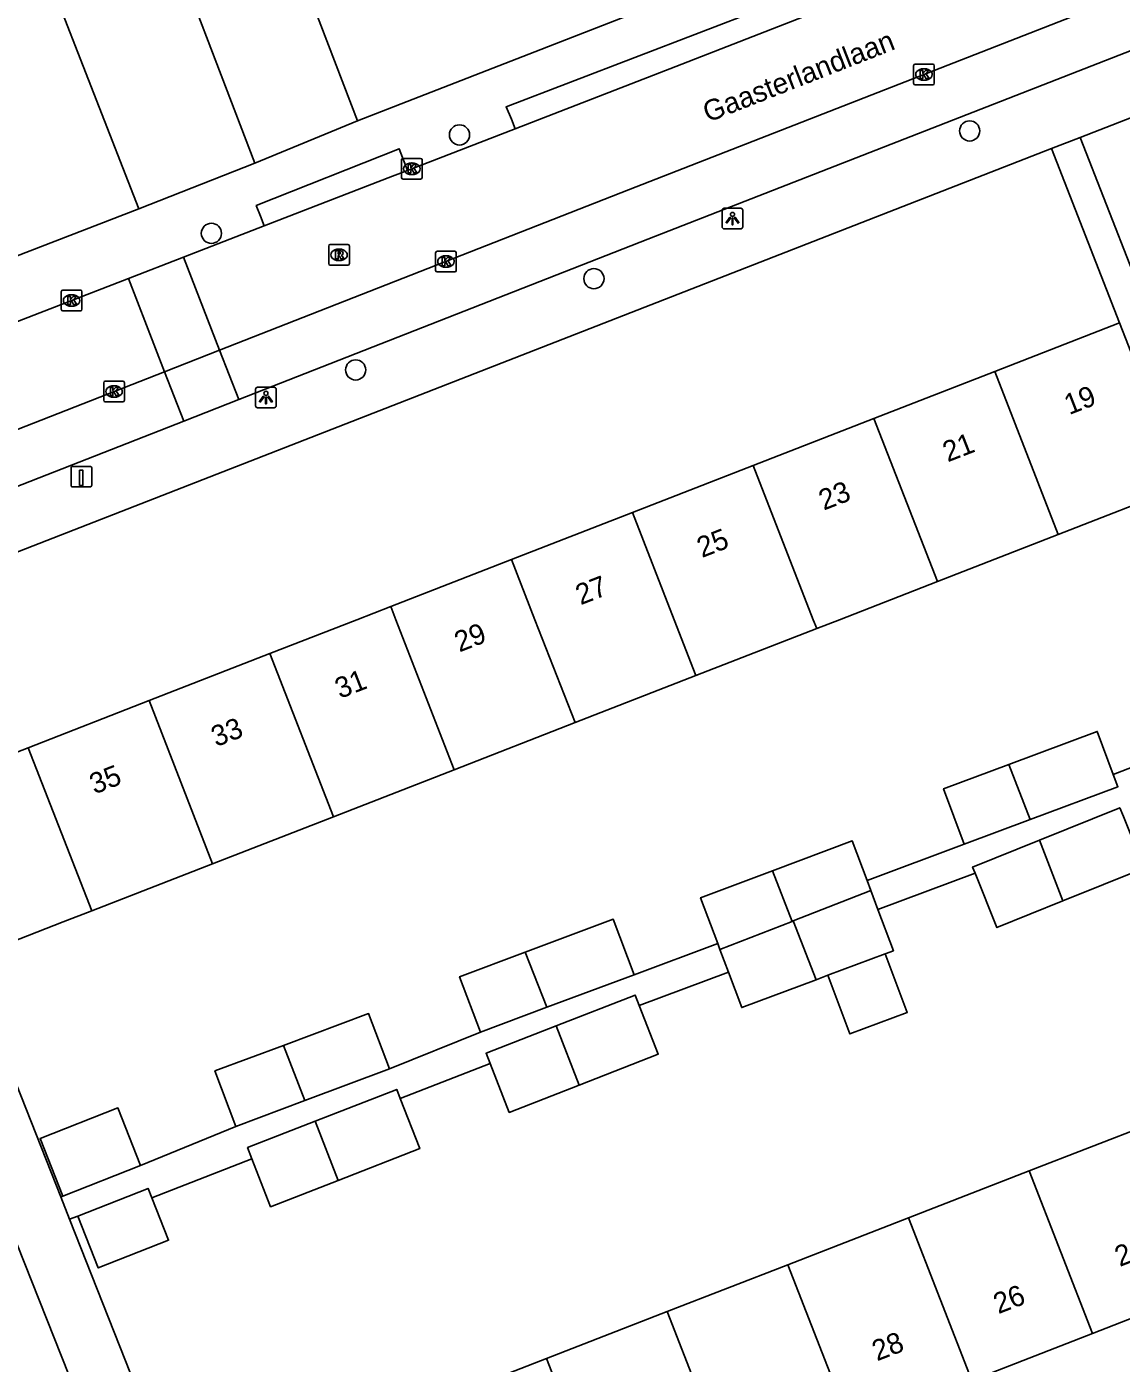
# Model space of a CAD drawing. Extents: x 159689 to 160786, y 387323 to 388339.
# Drawn here: x 160154.9 to 160207.9, y 387464 to 387528.7 of the extents above; entities that cross this region are included whole.
import ezdxf

# ---------------------------------------------------------------- set-up
doc = ezdxf.new("R2010")
doc.units = 0
for name, color, linetype in [('IMGEO_Boom', 7, 'Continuous'), ('IMGEO_Kolk', 7, 'Continuous'), ('IMGEO_Laadpaal', 7, 'Continuous'), ('IMGEO_Lichtpunt', 7, 'Continuous'), ('IMGEO_Openbare_ruimte_label', 7, 'Continuous'), ('IMGEO_Pand', 7, 'Continuous'), ('IMGEO_Pand_nummerreeks', 7, 'Continuous'), ('IMGEO_Parkeervlak_open', 7, 'Continuous'), ('IMGEO_Rijbaan_lokaal_open', 7, 'Continuous'), ('IMGEO_Rioolput', 7, 'Continuous'), ('IMGEO_Voetpad_open', 7, 'Continuous')]:
    doc.layers.add(name, color=color, linetype=linetype)

msp = doc.modelspace()

# ---------------------------------------------------------------- linework, layer by layer
at = {"layer": 'IMGEO_Boom'}
for centre in [(160175.85, 387523.495), (160200.56, 387523.687), (160163.832, 387518.725), (160182.362, 387516.53), (160170.821, 387512.106)]:
    msp.add_circle(centre, 0.489, dxfattribs=at)
at = {"layer": 'IMGEO_Kolk'}
for p, q in [((160197.847, 387525.996), (160197.847, 387526.848)), ((160197.922, 387526.922), (160198.774, 387526.922)), ((160198.335, 387526.702), (160198.36, 387526.702)), ((160198.848, 387526.848), (160198.848, 387525.996)), ((160198.774, 387525.922), (160197.922, 387525.922)), ((160198.358, 387526.142), (160198.333, 387526.142)), ((160173.042, 387521.428), (160173.042, 387522.28)), ((160173.117, 387522.354), (160173.969, 387522.354)), ((160173.53, 387522.134), (160173.555, 387522.134)), ((160174.043, 387522.28), (160174.043, 387521.428)), ((160173.553, 387521.574), (160173.528, 387521.574)), ((160173.969, 387521.354), (160173.117, 387521.354)), ((160174.695, 387516.933), (160174.695, 387517.785)), ((160174.77, 387517.859), (160175.622, 387517.859)), ((160175.183, 387517.639), (160175.208, 387517.639)), ((160175.696, 387517.785), (160175.696, 387516.933)), ((160175.622, 387516.859), (160174.77, 387516.859)), ((160175.206, 387517.079), (160175.181, 387517.079)), ((160156.563, 387515.046), (160156.563, 387515.898)), ((160156.638, 387515.972), (160157.49, 387515.972)), ((160157.051, 387515.752), (160157.076, 387515.752)), ((160157.564, 387515.898), (160157.564, 387515.046)), ((160157.49, 387514.972), (160156.638, 387514.972)), ((160157.074, 387515.192), (160157.049, 387515.192)), ((160158.617, 387510.635), (160158.617, 387511.487)), ((160158.692, 387511.561), (160159.544, 387511.561)), ((160159.105, 387511.341), (160159.13, 387511.341)), ((160159.618, 387511.487), (160159.618, 387510.635)), ((160159.544, 387510.561), (160158.692, 387510.561)), ((160159.128, 387510.781), (160159.103, 387510.781))]:
    msp.add_line(p, q, dxfattribs=at)
for points in [[(160197.847, 387525.996), (160197.847, 387526.848)], [(160197.922, 387526.922), (160198.774, 387526.922)], [(160198.168, 387526.622), (160198.291, 387526.622), (160198.291, 387526.471), (160198.421, 387526.622), (160198.585, 387526.622), (160198.439, 387526.471), (160198.592, 387526.222), (160198.44, 387526.222), (160198.355, 387526.386), (160198.291, 387526.319), (160198.291, 387526.222), (160198.168, 387526.222), (160198.168, 387526.622)], [(160198.848, 387526.848), (160198.848, 387525.996)], [(160198.774, 387525.922), (160197.922, 387525.922)], [(160173.042, 387521.428), (160173.042, 387522.28)], [(160173.117, 387522.354), (160173.969, 387522.354)], [(160173.363, 387522.054), (160173.486, 387522.054), (160173.486, 387521.903), (160173.616, 387522.054), (160173.78, 387522.054), (160173.634, 387521.903), (160173.787, 387521.654), (160173.635, 387521.654), (160173.55, 387521.818), (160173.486, 387521.751), (160173.486, 387521.654), (160173.363, 387521.654), (160173.363, 387522.054)], [(160174.043, 387522.28), (160174.043, 387521.428)], [(160173.969, 387521.354), (160173.117, 387521.354)], [(160174.695, 387516.933), (160174.695, 387517.785)], [(160174.77, 387517.859), (160175.622, 387517.859)], [(160175.016, 387517.559), (160175.139, 387517.559), (160175.139, 387517.408), (160175.269, 387517.559), (160175.433, 387517.559), (160175.287, 387517.408), (160175.44, 387517.159), (160175.288, 387517.159), (160175.203, 387517.323), (160175.139, 387517.256), (160175.139, 387517.159), (160175.016, 387517.159), (160175.016, 387517.559)], [(160175.696, 387517.785), (160175.696, 387516.933)], [(160175.622, 387516.859), (160174.77, 387516.859)], [(160156.563, 387515.046), (160156.563, 387515.898)], [(160156.638, 387515.972), (160157.49, 387515.972)], [(160156.884, 387515.672), (160157.007, 387515.672), (160157.007, 387515.521), (160157.137, 387515.672), (160157.301, 387515.672), (160157.155, 387515.521), (160157.308, 387515.272), (160157.156, 387515.272), (160157.071, 387515.436), (160157.007, 387515.369), (160157.007, 387515.272), (160156.884, 387515.272), (160156.884, 387515.672)], [(160157.564, 387515.898), (160157.564, 387515.046)], [(160157.49, 387514.972), (160156.638, 387514.972)], [(160158.617, 387510.635), (160158.617, 387511.487)], [(160158.692, 387511.561), (160159.544, 387511.561)], [(160158.938, 387511.261), (160159.061, 387511.261), (160159.061, 387511.11), (160159.191, 387511.261), (160159.355, 387511.261), (160159.209, 387511.11), (160159.362, 387510.861), (160159.21, 387510.861), (160159.125, 387511.025), (160159.061, 387510.958), (160159.061, 387510.861), (160158.938, 387510.861), (160158.938, 387511.261)], [(160159.618, 387511.487), (160159.618, 387510.635)], [(160159.544, 387510.561), (160158.692, 387510.561)]]:
    msp.add_lwpolyline(points, dxfattribs=at)
for centre, start, end in [((160197.924, 387526.846), 91.55205, 178.44795), ((160197.924, 387526.846), 91.55205, 178.44795), ((160198.772, 387526.846), 1.55205, 88.44795), ((160198.772, 387526.846), 1.55205, 88.44795), ((160197.924, 387525.998), 181.55205, 268.44795), ((160197.924, 387525.998), 181.55205, 268.44795), ((160198.772, 387525.998), 271.55205, 358.44795), ((160198.772, 387525.998), 271.55205, 358.44795), ((160173.119, 387522.278), 91.55205, 178.44795), ((160173.119, 387522.278), 91.55205, 178.44795), ((160173.967, 387522.278), 1.55205, 88.44795), ((160173.967, 387522.278), 1.55205, 88.44795), ((160173.119, 387521.43), 181.55205, 268.44795), ((160173.119, 387521.43), 181.55205, 268.44795), ((160173.967, 387521.43), 271.55205, 358.44795), ((160173.967, 387521.43), 271.55205, 358.44795), ((160174.772, 387517.783), 91.55205, 178.44795), ((160174.772, 387517.783), 91.55205, 178.44795), ((160175.62, 387517.783), 1.55205, 88.44795), ((160175.62, 387517.783), 1.55205, 88.44795), ((160174.772, 387516.935), 181.55205, 268.44795), ((160174.772, 387516.935), 181.55205, 268.44795), ((160175.62, 387516.935), 271.55205, 358.44795), ((160175.62, 387516.935), 271.55205, 358.44795), ((160156.64, 387515.896), 91.55205, 178.44795), ((160156.64, 387515.896), 91.55205, 178.44795), ((160157.488, 387515.896), 1.55205, 88.44795), ((160157.488, 387515.896), 1.55205, 88.44795), ((160156.64, 387515.048), 181.55205, 268.44795), ((160156.64, 387515.048), 181.55205, 268.44795), ((160157.488, 387515.048), 271.55205, 358.44795), ((160157.488, 387515.048), 271.55205, 358.44795), ((160158.694, 387511.485), 91.55205, 178.44795), ((160158.694, 387511.485), 91.55205, 178.44795), ((160159.542, 387511.485), 1.55205, 88.44795), ((160159.542, 387511.485), 1.55205, 88.44795), ((160158.694, 387510.637), 181.55205, 268.44795), ((160158.694, 387510.637), 181.55205, 268.44795), ((160159.542, 387510.637), 271.55205, 358.44795), ((160159.542, 387510.637), 271.55205, 358.44795)]:
    msp.add_arc(centre, 0.0765, start, end, dxfattribs=at)
for centre, major_axis, ratio, start_param, end_param in [((160198.334, 387526.422), (-0.387, 0.002), 0.722429, 4.712389, 7.853982), ((160198.359, 387526.422), (-0.39, 0.002), 0.717154, 1.570796, 4.712389), ((160173.529, 387521.854), (-0.387, 0.002), 0.722429, 4.712389, 7.853982), ((160173.554, 387521.854), (-0.39, 0.002), 0.717154, 1.570796, 4.712389), ((160175.182, 387517.359), (-0.387, 0.002), 0.722429, 4.712389, 7.853982), ((160175.207, 387517.359), (-0.39, 0.002), 0.717154, 1.570796, 4.712389), ((160157.05, 387515.472), (-0.387, 0.002), 0.722429, 4.712389, 7.853982), ((160157.075, 387515.472), (-0.39, 0.002), 0.717154, 1.570796, 4.712389), ((160159.104, 387511.061), (-0.387, 0.002), 0.722429, 4.712389, 7.853982), ((160159.129, 387511.061), (-0.39, 0.002), 0.717154, 1.570796, 4.712389)]:
    msp.add_ellipse(centre, major_axis=major_axis, ratio=ratio, start_param=start_param, end_param=end_param, dxfattribs=at)
at = {"layer": 'IMGEO_Laadpaal'}
for p, q in [((160157.035, 387507.351), (160157.035, 387506.51)), ((160157.035, 387507.351), (160157.035, 387506.51)), ((160157.951, 387507.435), (160157.11, 387507.435)), ((160157.951, 387507.435), (160157.11, 387507.435)), ((160158.035, 387506.519), (160158.035, 387507.36)), ((160158.035, 387506.519), (160158.035, 387507.36)), ((160157.119, 387506.435), (160157.96, 387506.435)), ((160157.119, 387506.435), (160157.96, 387506.435))]:
    msp.add_line(p, q, dxfattribs=at)
msp.add_lwpolyline([(160157.45, 387507.248), (160157.61, 387507.248), (160157.61, 387506.515), (160157.45, 387506.515), (160157.45, 387507.248)], dxfattribs=at)
for centre, start, end in [((160157.113, 387507.357), 92.4484, 184.28452), ((160157.113, 387507.357), 92.4484, 184.28452), ((160157.957, 387507.357), 2.4484, 94.28452), ((160157.957, 387507.357), 2.4484, 94.28452), ((160157.113, 387506.513), 182.4484, 274.28452), ((160157.113, 387506.513), 182.4484, 274.28452), ((160157.957, 387506.513), 272.4484, 4.28452), ((160157.957, 387506.513), 272.4484, 4.28452)]:
    msp.add_arc(centre, 0.0779, start, end, dxfattribs=at)
at = {"layer": 'IMGEO_Lichtpunt'}
for p, q in [((160188.573, 387519.845), (160188.573, 387519.038)), ((160188.573, 387519.845), (160188.573, 387519.038)), ((160189.475, 387519.94), (160188.667, 387519.94)), ((160189.475, 387519.94), (160188.667, 387519.94)), ((160189.569, 387519.038), (160189.569, 387519.845)), ((160189.569, 387519.038), (160189.569, 387519.845)), ((160188.667, 387518.944), (160189.475, 387518.944)), ((160188.667, 387518.944), (160189.475, 387518.944)), ((160165.974, 387511.174), (160165.974, 387510.367)), ((160165.974, 387511.174), (160165.974, 387510.367)), ((160166.876, 387511.269), (160166.068, 387511.269)), ((160166.876, 387511.269), (160166.068, 387511.269)), ((160166.97, 387510.367), (160166.97, 387511.174)), ((160166.97, 387510.367), (160166.97, 387511.174)), ((160166.068, 387510.273), (160166.876, 387510.273)), ((160166.068, 387510.273), (160166.876, 387510.273))]:
    msp.add_line(p, q, dxfattribs=at)
for points in [[(160188.947, 387519.509), (160188.986, 387519.481), (160188.798, 387519.219), (160188.76, 387519.246), (160188.947, 387519.509)], [(160189.049, 387519.461), (160189.096, 387519.461), (160189.096, 387519.139), (160189.049, 387519.139), (160189.049, 387519.461)], [(160189.159, 387519.481), (160189.197, 387519.508), (160189.384, 387519.246), (160189.345, 387519.218), (160189.159, 387519.481)], [(160166.348, 387510.838), (160166.387, 387510.81), (160166.199, 387510.548), (160166.161, 387510.575), (160166.348, 387510.838)], [(160166.45, 387510.79), (160166.497, 387510.79), (160166.497, 387510.468), (160166.45, 387510.468), (160166.45, 387510.79)], [(160166.56, 387510.81), (160166.598, 387510.837), (160166.785, 387510.575), (160166.746, 387510.547), (160166.56, 387510.81)]]:
    msp.add_lwpolyline(points, dxfattribs=at)
for centre in [(160189.072, 387519.643), (160166.473, 387510.972)]:
    msp.add_circle(centre, 0.0994, dxfattribs=at)
for centre, start, end in [((160188.667, 387519.845), 90, 180), ((160188.667, 387519.845), 90, 180), ((160189.475, 387519.845), 0, 90), ((160189.475, 387519.845), 0, 90), ((160188.667, 387519.038), 180, 270), ((160188.667, 387519.038), 180, 270), ((160189.475, 387519.038), 270, 0), ((160189.475, 387519.038), 270, 360), ((160166.068, 387511.174), 90, 180), ((160166.068, 387511.174), 90, 180), ((160166.876, 387511.174), 0, 90), ((160166.876, 387511.174), 0, 90), ((160166.068, 387510.367), 180, 270), ((160166.068, 387510.367), 180, 270), ((160166.876, 387510.367), 270, 0), ((160166.876, 387510.367), 270, 360)]:
    msp.add_arc(centre, 0.0946, start, end, dxfattribs=at)
at = {"layer": 'IMGEO_Pand'}
for points in [[(160201.778, 387512.033), (160207.825, 387514.388)], [(160207.825, 387514.388), (160209.639, 387509.729), (160210.902, 387506.485)], [(160195.926, 387509.755), (160201.778, 387512.033)], [(160201.778, 387512.033), (160204.855, 387504.13)], [(160190.074, 387507.476), (160195.926, 387509.755)], [(160199.003, 387501.852), (160195.926, 387509.755)], [(160184.222, 387505.197), (160190.074, 387507.476)], [(160193.152, 387499.573), (160192.985, 387500), (160190.074, 387507.476)], [(160210.902, 387506.485), (160204.855, 387504.13)], [(160178.371, 387502.918), (160184.222, 387505.197)], [(160184.222, 387505.197), (160186.246, 387500), (160187.3, 387497.294)], [(160204.855, 387504.13), (160199.003, 387501.852)], [(160172.518, 387500.639), (160178.371, 387502.918)], [(160178.371, 387502.918), (160179.507, 387500), (160181.448, 387495.016)], [(160199.003, 387501.852), (160194.248, 387500), (160193.152, 387499.573)], [(160166.666, 387498.361), (160170.876, 387500), (160172.518, 387500.639)], [(160175.595, 387492.737), (160172.767, 387500), (160172.518, 387500.639)], [(160193.152, 387499.573), (160187.3, 387497.294)], [(160160.814, 387496.082), (160166.666, 387498.361)], [(160169.743, 387490.458), (160166.666, 387498.361)], [(160187.3, 387497.294), (160181.448, 387495.016)], [(160154.962, 387493.803), (160160.814, 387496.082)], [(160160.814, 387496.082), (160163.891, 387488.179)], [(160181.448, 387495.016), (160175.595, 387492.737)], [(160207.517, 387492.511), (160206.738, 387494.594), (160202.453, 387492.991)], [(160148.917, 387491.449), (160154.962, 387493.803)], [(160158.039, 387485.9), (160154.962, 387493.803)], [(160200.3, 387489.126), (160199.296, 387491.811), (160202.453, 387492.991)], [(160202.453, 387492.991), (160203.493, 387490.32)], [(160175.595, 387492.737), (160169.743, 387490.458)], [(160203.493, 387490.32), (160207.742, 387491.909), (160207.517, 387492.511)], [(160169.743, 387490.458), (160163.891, 387488.179)], [(160203.493, 387490.32), (160200.3, 387489.126)], [(160208.004, 387490.464), (160207.83, 387490.896), (160203.935, 387489.324)], [(160208.004, 387490.464), (160209.013, 387487.963), (160205.081, 387486.376)], [(160195.594, 387487.365), (160194.876, 387489.283), (160191.004, 387487.833)], [(160203.935, 387489.324), (160200.7, 387488.019), (160200.82, 387487.721)], [(160203.935, 387489.324), (160205.081, 387486.376)], [(160163.891, 387488.179), (160158.039, 387485.9)], [(160191.004, 387487.833), (160187.527, 387486.531), (160188.355, 387484.32)], [(160191.956, 387485.388), (160191.004, 387487.833)], [(160205.081, 387486.376), (160201.883, 387485.086), (160200.82, 387487.721)], [(160195.774, 387486.883), (160195.594, 387487.365)], [(160195.774, 387486.883), (160192.016, 387485.411)], [(160196.12, 387485.96), (160195.774, 387486.883)], [(160158.039, 387485.9), (160156.654, 387485.361), (160151.994, 387483.546)], [(160196.472, 387483.816), (160196.868, 387483.964), (160196.12, 387485.96)], [(160179.038, 387483.894), (160183.301, 387485.488), (160184.305, 387482.804)], [(160191.956, 387485.388), (160188.466, 387484.022)], [(160192.016, 387485.411), (160191.956, 387485.388)], [(160192.016, 387485.411), (160193.124, 387482.562)], [(160176.862, 387480.02), (160175.858, 387482.705), (160179.038, 387483.894)], [(160179.038, 387483.894), (160180.078, 387481.223)], [(160188.355, 387484.32), (160188.466, 387484.022)], [(160188.466, 387484.022), (160188.876, 387482.928)], [(160193.693, 387482.775), (160196.472, 387483.816)], [(160193.693, 387482.775), (160194.756, 387479.935), (160197.535, 387480.976), (160196.472, 387483.816)], [(160184.305, 387482.804), (160180.078, 387481.223)], [(160193.124, 387482.562), (160189.519, 387481.212), (160188.876, 387482.928)], [(160193.124, 387482.562), (160193.693, 387482.775)], [(160180.526, 387480.319), (160184.363, 387481.814), (160184.559, 387481.31)], [(160184.559, 387481.31), (160185.48, 387478.946), (160181.641, 387477.45)], [(160167.318, 387479.378), (160171.449, 387480.922), (160172.453, 387478.238)], [(160180.078, 387481.223), (160176.862, 387480.02)], [(160180.526, 387480.319), (160177.139, 387478.999), (160177.335, 387478.497)], [(160181.641, 387477.45), (160180.526, 387480.319)], [(160165.01, 387475.455), (160164.006, 387478.139), (160167.318, 387479.378)], [(160167.318, 387479.378), (160168.358, 387476.706)], [(160172.453, 387478.238), (160168.358, 387476.706)], [(160181.641, 387477.45), (160178.257, 387476.131), (160177.335, 387478.497)], [(160168.358, 387476.706), (160165.01, 387475.455)], [(160172.981, 387476.801), (160172.809, 387477.243), (160168.864, 387475.706)], [(160172.981, 387476.801), (160173.926, 387474.375), (160169.979, 387472.837)], [(160156.638, 387472.073), (160155.538, 387474.866), (160159.306, 387476.351), (160160.407, 387473.559)], [(160165.798, 387473.883), (160165.585, 387474.429), (160168.864, 387475.706)], [(160168.864, 387475.706), (160169.979, 387472.837)], [(160203.439, 387473.294), (160209.283, 387475.567)], [(160160.407, 387473.559), (160156.638, 387472.073)], [(160169.979, 387472.837), (160166.703, 387471.561), (160165.798, 387473.883)], [(160197.595, 387471.022), (160203.439, 387473.294)], [(160206.502, 387465.417), (160203.439, 387473.294)], [(160157.359, 387471.106), (160160.768, 387472.451), (160160.949, 387471.993)], [(160160.949, 387471.993), (160161.758, 387469.94), (160158.35, 387468.596), (160157.359, 387471.106)], [(160191.752, 387468.75), (160197.595, 387471.022)], [(160197.595, 387471.022), (160200.658, 387463.145)], [(160185.908, 387466.477), (160191.752, 387468.75)], [(160191.752, 387468.75), (160194.815, 387460.872)], [(160212.345, 387467.69), (160206.502, 387465.417)], [(160180.064, 387464.205), (160185.908, 387466.477)], [(160185.908, 387466.477), (160188.971, 387458.6)], [(160206.502, 387465.417), (160200.658, 387463.145)], [(160174.22, 387461.932), (160180.064, 387464.205)], [(160183.127, 387456.327), (160180.064, 387464.205)]]:
    msp.add_lwpolyline(points, dxfattribs=at)
at = {"layer": 'IMGEO_Parkeervlak_open'}
for points in [[(160160.319, 387519.908), (160155.964, 387531.114)], [(160164.229, 387513.065), (160165.156, 387510.671)], [(160162.493, 387509.628), (160161.566, 387512.022)]]:
    msp.add_lwpolyline(points, dxfattribs=at)
at = {"layer": 'IMGEO_Rijbaan_lokaal_open'}
for points in [[(160170.912, 387524.176), (160165.953, 387537.124)], [(160161.041, 387534.941), (160165.929, 387522.126)], [(160215.929, 387533.301), (160184.042, 387520.827), (160164.229, 387513.065)], [(160194.083, 387529.836), (160186.324, 387526.803), (160178.552, 387523.793)], [(160165.929, 387522.126), (160170.912, 387524.176)], [(160173.337, 387521.773), (160178.552, 387523.793)], [(160173.337, 387521.773), (160172.608, 387521.491), (160166.397, 387519.086)], [(160162.484, 387517.571), (160166.397, 387519.086)], [(160159.817, 387516.538), (160162.484, 387517.571)], [(160164.229, 387513.065), (160162.484, 387517.571)], [(160114.963, 387499.225), (160115.753, 387499.45), (160118.881, 387500.649), (160128.018, 387504.049), (160143.253, 387510.123), (160159.817, 387516.538)], [(160161.566, 387512.022), (160159.817, 387516.538)], [(160161.566, 387512.022), (160164.229, 387513.065)], [(160142.628, 387504.592), (160144.534, 387505.349), (160161.566, 387512.022)]]:
    msp.add_lwpolyline(points, dxfattribs=at)
at = {"layer": 'IMGEO_Rioolput'}
for p, q in [((160169.589, 387518.183), (160170.441, 387518.183)), ((160169.514, 387517.257), (160169.514, 387518.109)), ((160170.002, 387517.963), (160170.027, 387517.963)), ((160170.515, 387518.109), (160170.515, 387517.257)), ((160170.441, 387517.183), (160169.589, 387517.183)), ((160170.025, 387517.403), (160170, 387517.403))]:
    msp.add_line(p, q, dxfattribs=at)
for points in [[(160169.589, 387518.183), (160170.441, 387518.183)], [(160169.514, 387517.257), (160169.514, 387518.109)], [(160170.103, 387517.881), (160169.851, 387517.883), (160169.851, 387517.483)], [(160169.851, 387517.483), (160169.975, 387517.483), (160169.975, 387517.645), (160169.986, 387517.645)], [(160170.029, 387517.802), (160169.975, 387517.802), (160169.975, 387517.721)], [(160169.975, 387517.721), (160170.027, 387517.721)], [(160170.033, 387517.616), (160170.104, 387517.483), (160170.244, 387517.483), (160170.179, 387517.609)], [(160170.515, 387518.109), (160170.515, 387517.257)], [(160170.441, 387517.183), (160169.589, 387517.183)]]:
    msp.add_lwpolyline(points, dxfattribs=at)
for centre, radius, start, end in [((160169.591, 387518.107), 0.0765, 91.55205, 178.44795), ((160169.591, 387518.107), 0.0765, 91.55205, 178.44795), ((160170.439, 387518.107), 0.0765, 1.55205, 88.44795), ((160170.439, 387518.107), 0.0765, 1.55205, 88.44795), ((160169.985, 387517.592), 0.0533, 26.02933, 88.69889), ((160170.011, 387517.91), 0.19, 274.7715, 282.96867), ((160170.035, 387517.706), 0.0964, 77.00612, 93.18647), ((160170.049, 387517.763), 0.0378, 276.66336, 79.67722), ((160170.102, 387517.771), 0.109, 350.36119, 89.41601), ((160170.1, 387517.771), 0.112, 277.58423, 350.98172), ((160170.084, 387517.556), 0.108, 29.51342, 73.79051), ((160169.591, 387517.259), 0.0765, 181.55205, 268.44795), ((160169.591, 387517.259), 0.0765, 181.55205, 268.44795), ((160170.439, 387517.259), 0.0765, 271.55205, 358.44795), ((160170.439, 387517.259), 0.0765, 271.55205, 358.44795)]:
    msp.add_arc(centre, radius, start, end, dxfattribs=at)
for centre, major_axis, ratio, start_param, end_param in [((160170.001, 387517.683), (-0.387, 0.002), 0.722429, 4.712389, 7.853982), ((160170.026, 387517.683), (-0.39, 0.002), 0.717154, 1.570796, 4.712389)]:
    msp.add_ellipse(centre, major_axis=major_axis, ratio=ratio, start_param=start_param, end_param=end_param, dxfattribs=at)
at = {"layer": 'IMGEO_Voetpad_open'}
for points in [[(160205.916, 387523.37), (160259.073, 387544.104)], [(160192.897, 387532.748), (160170.912, 387524.176)], [(160216.863, 387530.909), (160184.978, 387518.436), (160165.156, 387510.671)], [(160178.552, 387523.793), (160178.369, 387524.257), (160178.108, 387524.848), (160193.692, 387530.842), (160193.9, 387530.3), (160194.083, 387529.836)], [(160204.532, 387522.83), (160205.916, 387523.37)], [(160205.916, 387523.37), (160208.461, 387516.845)], [(160145.626, 387499.854), (160204.532, 387522.83)], [(160166.397, 387519.086), (160166.214, 387519.551), (160166.009, 387520.071), (160172.93, 387522.822), (160173.337, 387521.773)], [(160207.825, 387514.388), (160204.532, 387522.83)], [(160165.929, 387522.126), (160160.319, 387519.908)], [(160113.221, 387501.712), (160160.319, 387519.908)], [(160165.156, 387510.671), (160162.493, 387509.628)], [(160162.493, 387509.628), (160146.454, 387503.345)], [(160141.985, 387501.105), (160142.423, 387500), (160142.953, 387498.663), (160156.933, 387463.411)], [(160211.818, 387494.172), (160207.517, 387492.511)], [(160200.3, 387489.126), (160195.594, 387487.365)], [(160200.82, 387487.721), (160196.12, 387485.96)], [(160188.355, 387484.32), (160184.305, 387482.804)], [(160156.541, 387472.034), (160151.994, 387483.546)], [(160188.876, 387482.928), (160184.559, 387481.31)], [(160176.862, 387480.02), (160172.453, 387478.238)], [(160177.335, 387478.497), (160172.981, 387476.801)], [(160165.01, 387475.455), (160160.407, 387473.559)], [(160165.798, 387473.883), (160160.949, 387471.993)], [(160156.638, 387472.073), (160156.541, 387472.034)], [(160156.968, 387470.952), (160156.541, 387472.034)], [(160157.359, 387471.106), (160156.968, 387470.952)], [(160162.353, 387457.317), (160156.968, 387470.952)]]:
    msp.add_lwpolyline(points, dxfattribs=at)

# ---------------------------------------------------------------- texts
at = {"layer": 'IMGEO_Openbare_ruimte_label'}
msp.add_text('Gaasterlandlaan', height=1, rotation=21.40774, dxfattribs=at).set_placement((160187.883, 387524.088))
at = {"layer": 'IMGEO_Pand_nummerreeks'}
for s, rotation, p in [('19', 21.27602, (160205.38, 387509.916)), ('21', 21.27602, (160199.499, 387507.626)), ('23', 21.27602, (160193.494, 387505.287)), ('25', 21.27602, (160187.593, 387502.99)), ('27', 21.27602, (160181.717, 387500.701)), ('29', 21.27631, (160175.847, 387498.416)), ('31', 21.27631, (160170.061, 387496.163)), ('33', 21.27631, (160164.065, 387493.828)), ('35', 21.27631, (160158.174, 387491.534)), ('24', 21.24975, (160207.831, 387468.638)), ('26', 21.24975, (160201.952, 387466.351)), ('28', 21.24975, (160196.075, 387464.066))]:
    msp.add_text(s, height=1, rotation=rotation, dxfattribs=at).set_placement(p)

doc.saveas('drawing.dxf')
